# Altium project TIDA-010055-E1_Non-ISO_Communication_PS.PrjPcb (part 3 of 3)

## Sheet TIDA-010055-E1_Non-ISO_Communication_PS_Pg6.SchDoc
size 431 x 279 mm; Date: Not shown in title block; ApprovedBy: Not shown in title block; CheckedBy: Not shown in title block; Author: Not shown in title block; CompanyName: Not shown in title block; Engineer: Not shown in title block; Organization: Not shown in title block; Address1: Not shown in title block; Address2: Not shown in title block; Address3: Not shown in title block; Address4: Not shown in title block; DocumentNumber: 1; Revision: Use project parameter SCH_Rev; SheetNumber: 6; SheetTotal: 7; PageSetup: Record=PageOptions¦CenterHorizontal=True¦CenterVertical=True¦PrintScale=1.00¦XCorrection=1.00¦YCorrection=1.00¦PrintKind=0¦BorderSize=5000000¦LeftOffset=0¦BottomOffset=0¦Orientation=2¦PaperLength=1000¦PaperWidth=1000¦Scale=100¦PaperSource=15¦PrintQuality=600¦MediaType=1¦DitherType=10¦PaperKind=Letter¦PrintScaleMode=1
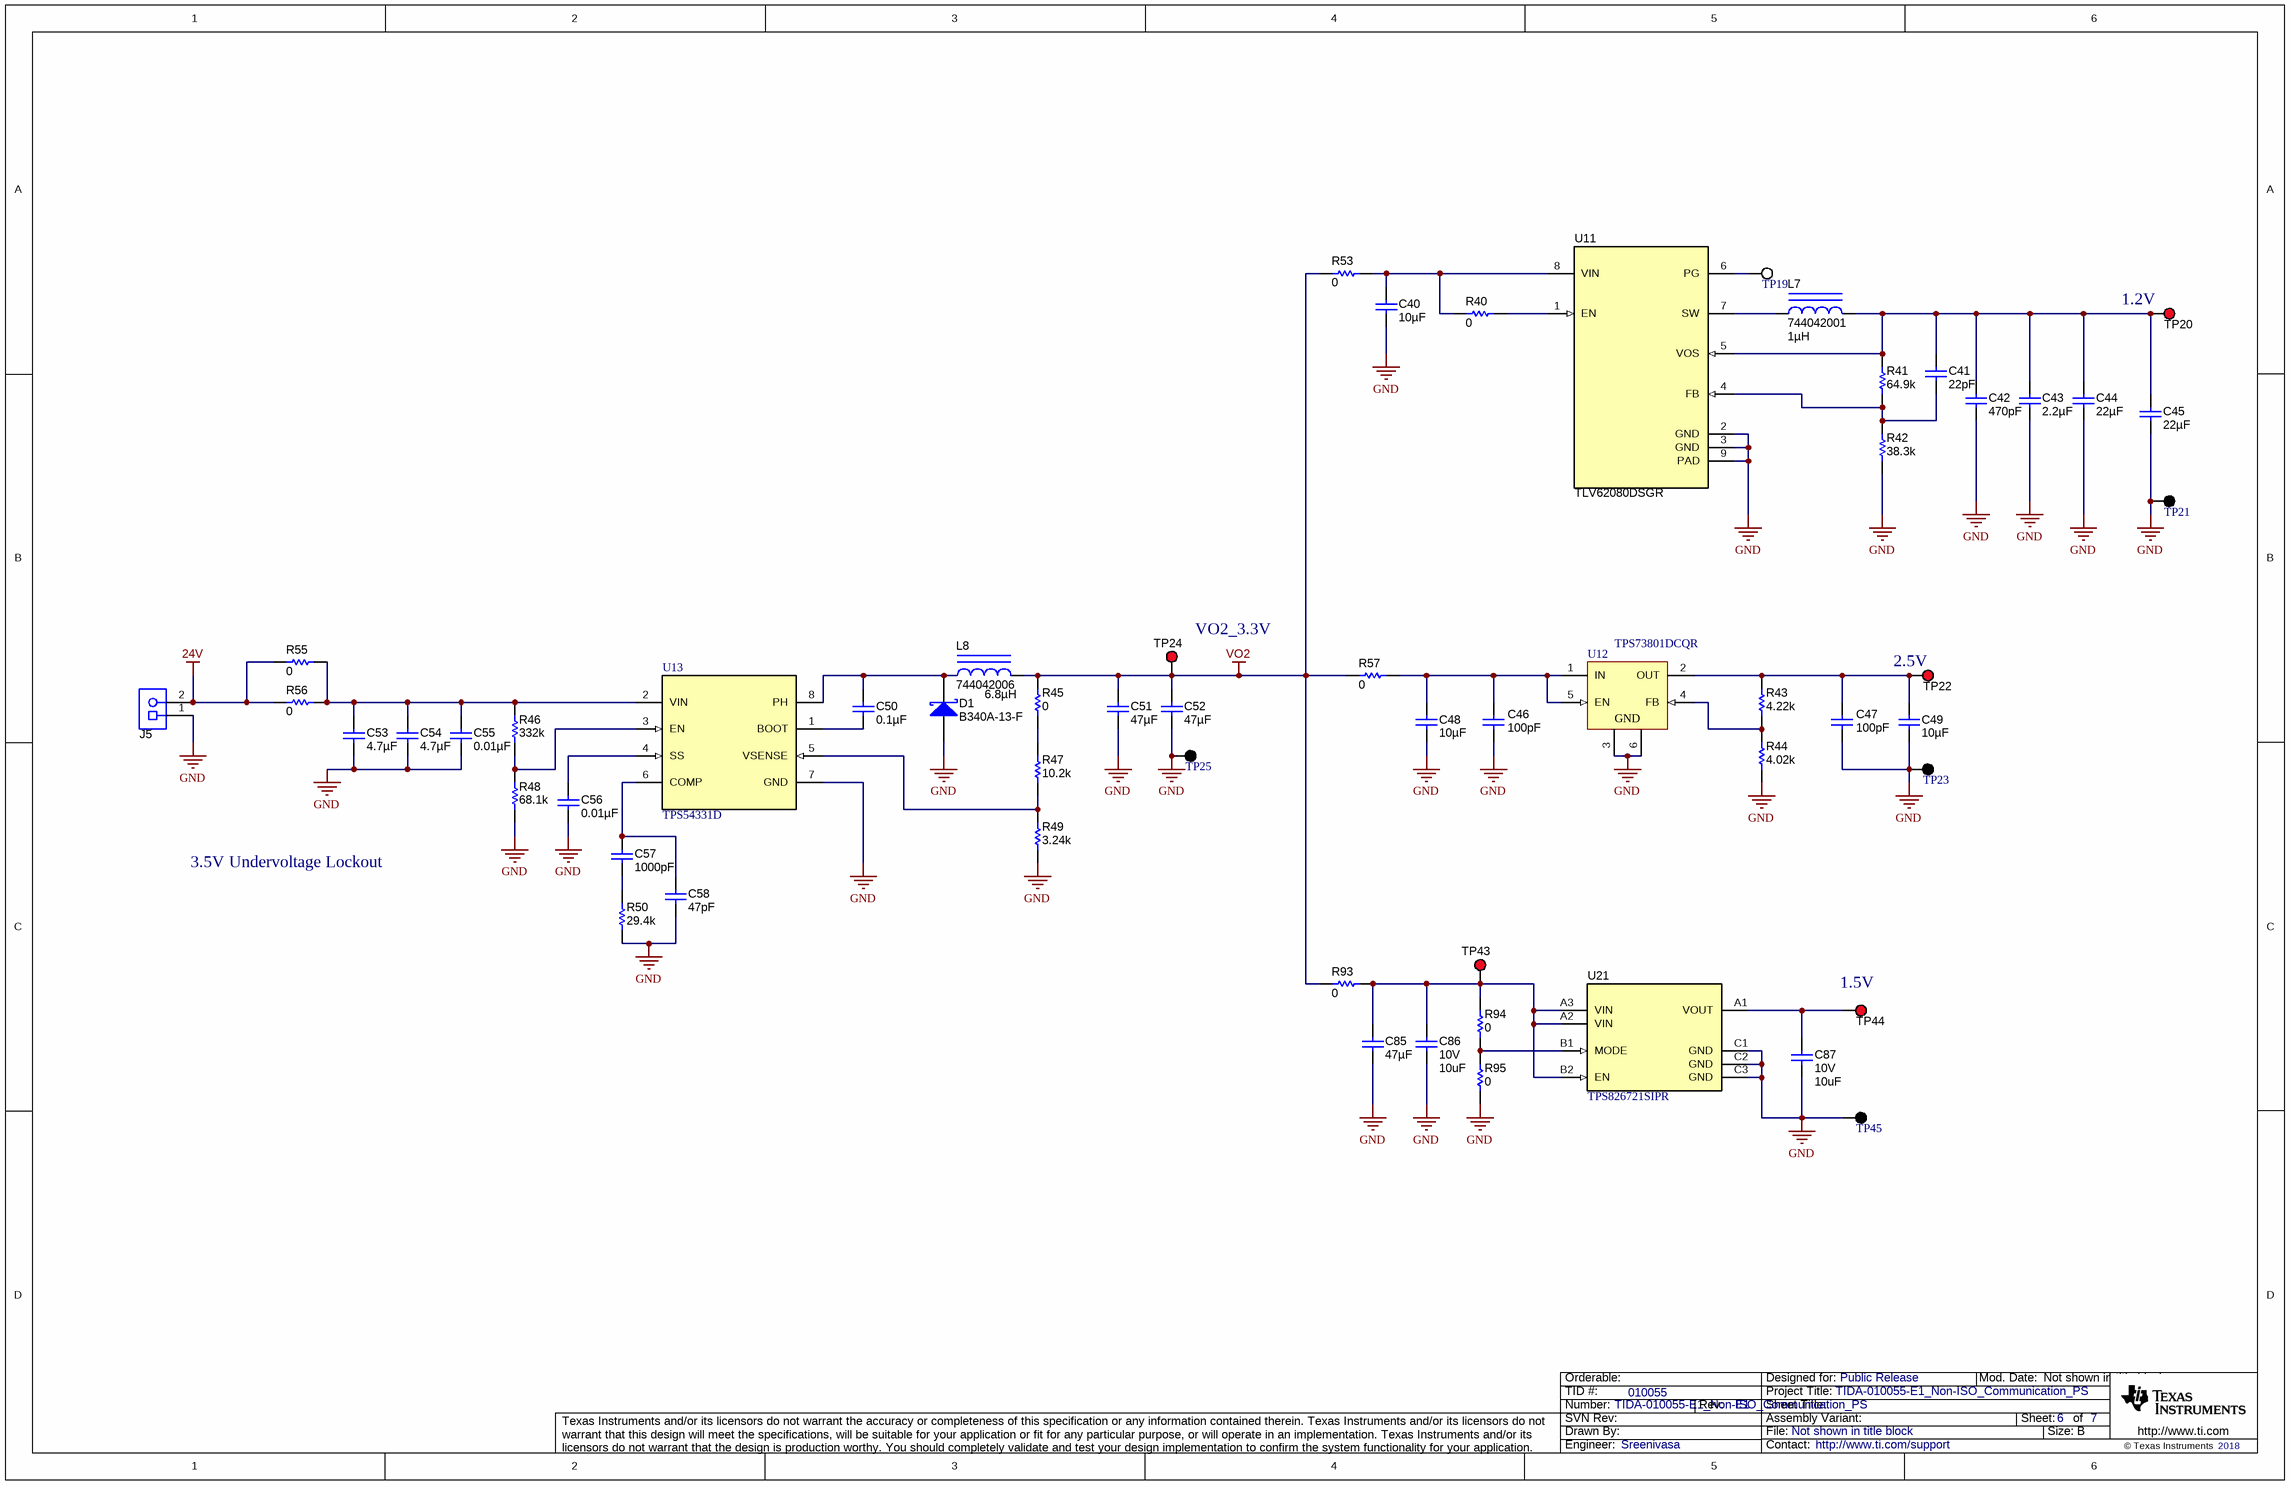
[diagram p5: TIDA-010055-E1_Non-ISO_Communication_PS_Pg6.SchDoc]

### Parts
C40  ValueDisplayed: 10µF  [0603]  (hidden comment: CL10A106MQ8NNNC)
C41  ValueDisplayed: 22pF  [0402]  (hidden comment: CL05C220JB51PNC)
C42  ValueDisplayed: 470pF  [0402]  (hidden comment: GCM155R71H471KA37D)
C43  ValueDisplayed: 2.2µF  [0603]  (hidden comment: 885012106018)
C44  ValueDisplayed: 22µF  [0805_HV1]  (hidden comment: CL21A226KQCLRNC)
C45  ValueDisplayed: 22µF  [0805_HV1]  (hidden comment: CL21A226KQCLRNC)
C46  ValueDisplayed: 100pF  [0603]  (hidden comment: 06031A101GAT2A)
C47  ValueDisplayed: 100pF  [0603]  (hidden comment: 06031A101GAT2A)
C48  ValueDisplayed: 10µF  [0805_HV]  (hidden comment: C2012X5R1E106K085AC)
C49  ValueDisplayed: 10µF  [0805_HV]  (hidden comment: C2012X5R1E106K085AC)
C50  ValueDisplayed: 0.1µF  [0805_HV]  (hidden comment: C0805C104K3RACTU)
C51  ValueDisplayed: 47µF  [0603]  (hidden comment: GRM188R60J476ME15D)
C52  ValueDisplayed: 47µF  [0603]  (hidden comment: GRM188R60J476ME15D)
C53  ValueDisplayed: 4.7µF  [0805_HV]  (hidden comment: C2012X7R1E475K125AB)
C54  ValueDisplayed: 4.7µF  [0805_HV]  (hidden comment: C2012X7R1E475K125AB)
C55  ValueDisplayed: 0.01µF  [0805_HV]  (hidden comment: 08055C103JAT2A)
C56  ValueDisplayed: 0.01µF  [0402]  (hidden comment: C0402C103K4PAC7867)
C57  ValueDisplayed: 1000pF  [0603]  (hidden comment: 06035A102KAT2A)
C58  ValueDisplayed: 47pF  [0603]  (hidden comment: 06035A470KAT2A)
C85  ValueDisplayed: 47µF  [1206_190L]  (hidden comment: CL31A476MPHNNNE)
C86  VDC_V: 10V  ValueDisplayed: 10uF  [0805L]  (hidden comment: GRM21BR71A106ME51L)
C87  VDC_V: 10V  ValueDisplayed: 10uF  [0805L]  (hidden comment: GRM21BR71A106ME51L)
D1  B340A-13-F  [SMA]
J5  1751248  [CONN_1751248]  (value not drawn)
L7  744042001  ValueDisplayed: 1µH  [WE-TPC-M1]
L8  744042006  ValueDisplayed: 6.8µH  [WE-TPC-M1]
R40  ValueDisplayed: 0  [0603]  (hidden comment: CRCW06030000Z0EA)
R41  ValueDisplayed: 64.9k  [0603]  (hidden comment: RC0603FR-0764K9L)
R42  ValueDisplayed: 38.3k  [0603]  (hidden comment: RC0603FR-0738K3L)
R43  ValueDisplayed: 4.22k  [0603]  (hidden comment: CRCW06034K22FKEA)
R44  ValueDisplayed: 4.02k  [0603]  (hidden comment: CRCW06034K02FKEA)
R45  ValueDisplayed: 0  [0603]  (hidden comment: CRCW06030000Z0EA)
R46  ValueDisplayed: 332k  [0603]  (hidden comment: CRCW0603332KFKEA)
R47  ValueDisplayed: 10.2k  [0603]  (hidden comment: CRCW060310K2FKEA)
R48  ValueDisplayed: 68.1k  [0603]  (hidden comment: RC0603FR-0768K1L)
R49  ValueDisplayed: 3.24k  [0603]  (hidden comment: CRCW06033K24FKEA)
R50  ValueDisplayed: 29.4k  [0603]  (hidden comment: RC0603FR-0729K4L)
R53  ValueDisplayed: 0  [5108]  (hidden comment: 5108)
R55  ValueDisplayed: 0  [5108]  (hidden comment: 5108)
R56  ValueDisplayed: 0  [5108]  (hidden comment: 5108)
R57  ValueDisplayed: 0  [5108]  (hidden comment: 5108)
R93  ValueDisplayed: 0  [5108]  (hidden comment: 5108)
R94  ValueDisplayed: 0  [0603]  (hidden comment: CRCW06030000Z0EA)
R95  ValueDisplayed: 0  [0603]  (hidden comment: CRCW06030000Z0EA)
TP19  5002  [Keystone5002]  (value not drawn)
TP20  5000  [Keystone5000]  (value not drawn)
TP21  5001  [Keystone5001]  (value not drawn)
TP22  5000  [Keystone5000]  (value not drawn)
TP23  5001  [Keystone5001]  (value not drawn)
TP24  5000  [Keystone5000]  (value not drawn)
TP25  5001  [Keystone5001]  (value not drawn)
TP43  5000  [Keystone5000]  (value not drawn)
TP44  5000  [Keystone5000]  (value not drawn)
TP45  5001  [Keystone5001]  (value not drawn)
U11  TLV62080DSGR  [DSG0008A]
U12  TPS73801DCQR  [DCQ0006A_N]
U13  TPS54331D  [D0008A_N]
U21  TPS826721SIPR  [SIP0008A]

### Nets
24V: J5.2 R55.2 R56.2
GND: C40.2 C42.2 C43.2 C44.2 C45.2 C46.1 C47.1 C48.1 C49.1 C51.2 C52.2 C53.2 C54.2 C55.2 C56.2 C58.2 C85.2 C86.2 C87.2 D1.2(A) J5.1 R42.1 R44.1 R48.1 R49.1 R50.1 R95.1 TP21.1 TP23.1 TP25.1 TP45.1 U11.2(GND) U11.3(GND) U11.9(PAD) U12.3(GND) U12.6(GND) U13.7(GND) U21.C1(GND) U21.C2(GND) U21.C3(GND)
VO2: C51.1 C52.1 L8.2 R45.2 R53.2 R57.2 R93.2 TP24.1
NetC40_1: C40.1 R40.1 R53.1 U11.8(VIN)
NetC41_1: C41.1 C42.1 C43.1 C44.1 C45.1 L7.2 R41.2 TP20.1 U11.5(VOS)
NetC41_2: C41.2 R41.1 R42.2 U11.4(FB)
NetC46_2: C46.2 C48.2 R57.1 U12.1(IN) U12.5(EN)
NetC47_2: C47.2 C49.2 R43.2 TP22.1 U12.2(OUT)
NetC50_1: C50.1 D1.1(K) L8.1 U13.8(PH)
NetC50_2: C50.2 U13.1(BOOT)
NetC53_1: C53.1 C54.1 C55.1 R46.2 R55.1 R56.1 U13.2(VIN)
NetC56_1: C56.1 U13.4(SS)
NetC57_1: C57.1 C58.1 U13.6(COMP)
NetC57_2: C57.2 R50.2
NetC85_1: C85.1 C86.1 R93.1 R94.2 TP43.1 U21.A2(VIN) U21.A3(VIN) U21.B2(EN)
NetC87_1: C87.1 TP44.1 U21.A1(VOUT)
NetL7_1: L7.1 U11.7(SW)
NetR40_2: R40.2 U11.1(EN)
NetR43_1: R43.1 R44.2 U12.4(FB)
NetR45_1: R45.1 R47.2
NetR46_1: R46.1 R48.2 U13.3(EN)
NetR47_1: R47.1 R49.2 U13.5(VSENSE)
NetR94_1: R94.1 R95.2 U21.B1(MODE)
NetTP19_1: TP19.1 U11.6(PG)

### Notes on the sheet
- (near TP20) 1.2V
- (near TP24) VO2_3.3V
- (near TP22) 2.5V
- 3.5V Undervoltage Lockout
- (near TP44) 1.5V

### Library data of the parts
C40 = GRM188R60J106ME84: CAP, CERM, 10 µF, 6.3 V, +/- 20%, X5R, 0603; Manufacturer: Samsung Electro-Mechanics; Polarized: N; CompType: Capacitor; Value: 10uF; U/M: EA; Cap_F: 0.00001; Tolerance_%: 20; Value1: Unknown; VDC_V: 6.3; Value2: 6.3V; TaMin_C: -55; TaMax_C: 85; AEC Category: Q200
C41 = GRM1555C1H220FA01D: CAP, CERM, 22 pF, 50 V, +/- 1%, C0G/NP0, 0402; Manufacturer: Samsung Electro-Mechanics; Polarized: N; CompType: Capacitor; Value: 22pF; U/M: EA; Cap_F: 0.000000000022; Tolerance_%: 1; Value1: Unknown; VDC_V: 50; Value2: 50V; TaMin_C: -55; TaMax_C: 125; AEC Category: Q200
C42 = GCM155R71H471KA37D: CAP, CERM, 470 pF, 50 V, +/- 10%, X7R, AEC-Q200 Grade 1, 0402; Manufacturer: MuRata; Polarized: N; CompType: Capacitor; Value: 470pF; U/M: EA; Cap_F: 0.00000000047; Tolerance_%: 10; Value1: Unknown; VDC_V: 50; Value2: 50V; TaMin_C: -55; TaMax_C: 125; AEC Category: Q200; AEC Qualified: Y; AEC Grade: 1
C43 = 885012106018: CAP, CERM, 2.2 µF, 16 V,+/- 20%, X5R, 0603; Manufacturer: Wurth Elektronik; Polarized: N; CompType: Capacitor; Value: 2.2uF; U/M: EA; Cap_F: 0.0000022; Tolerance_%: 20; VDC_V: 16; Value2: 16V; TaMin_C: -55; TaMax_C: 85; SizeArea_mm2: 1.28; SizeAreaWB_mm2: 4.68; SizeX_mm: 1.6; SizeY_mm: 0.8; SizeZ_mm: 1; AEC Category: Q200; Green_Lifecycle: Not Set; Green_REACh: Incomplete
C44 C45 = GRM21BR60J226ME39L: CAP, CERM, 22 µF, 6.3 V, +/- 20%, X5R, 0805; Manufacturer: Samsung Electro-Mechanics; Polarized: N; CompType: Capacitor; Value: 22uF; U/M: EA; Cap_F: 0.000022; Tolerance_%: 20; ESR_ohm: 0.009; Value1: 0.009 ohm; VDC_V: 6.3; Value2: 6.3V; IRMS_A: 3.5; TaMin_C: -55; TaMax_C: 85; Cap_Case: 0805; AEC Category: Q200
C46 C47 = 06035A101JAT2A: CAP, CERM, 100 pF, 50 V, +/- 5%, C0G/NP0, 0603; Manufacturer: AVX; Polarized: N; CompType: Capacitor; Value: 100pF; U/M: EA; Cap_F: 0.0000000001; Tolerance_%: 5; ESR_ohm: 0.119; Value1: 0.119 ohm; VDC_V: 50; Value2: 50V; TaMin_C: -55; TaMax_C: 125; SizeArea_mm2: 1.28; SizeAreaWB_mm2: 4.68; SizeX_mm: 1.6; SizeY_mm: 0.8; SizeZ_mm: 1; AEC Category: Q200
C48 C49 = GRM21BR61E106KA73L: CAP, CERM, 10 µF, 25 V, +/- 10%, X5R, 0805; Manufacturer: TDK Corporation; Polarized: N; CompType: Capacitor; Value: 10uF; U/M: EA; Cap_F: 0.00001; Tolerance_%: 10; Value1: Unknown; VDC_V: 25; Value2: 25V; TaMin_C: -55; TaMax_C: 85; Cap_Case: 0805; AEC Category: Q200
C50 = GRM21BR71E104KA01L: CAP, CERM, 0.1 µF, 25 V, +/- 10%, X7R, 0805; Manufacturer: KEMET; Polarized: N; CompType: Capacitor; Value: 0.1uF; U/M: EA; Cap_F: 0.0000001; Tolerance_%: 10; Value1: Unknown; VDC_V: 25; Value2: 25V; TaMin_C: -55; TaMax_C: 125; Cap_Case: 0805; AEC Category: Q200
C51 C52 = GRM188R60J476ME15D: CAP, CERM, 47 µF, 6.3 V,+/- 20%, X5R, 0603; Manufacturer: MuRata; Polarized: N; CompType: Capacitor; Value: 47uF; U/M: EA; Cap_F: 0.000047; Tolerance_%: 20; VDC_V: 6.3; Value2: 6.3V; TaMin_C: -55; TaMax_C: 85; SizeArea_mm2: 1.28; SizeAreaWB_mm2: 4.68; SizeX_mm: 1.6; SizeY_mm: 0.8; SizeZ_mm: 1; AEC Category: Q200; Green_Lifecycle: Active; Green_REACh: Passed
C53 C54 = GRM21BR71E475KA73L: CAP, CERM, 4.7 µF, 25 V,+/- 10%, X7R, 0805; Manufacturer: TDK Corporation; Polarized: N; CompType: Capacitor; Value: 4.7uF; U/M: EA; Cap_F: 0.0000047; Tolerance_%: 10; VDC_V: 25; Value2: 25V; TaMin_C: -55; TaMax_C: 125; Cap_Case: 0805; SizeArea_mm2: 2.5; SizeAreaWB_mm2: 6.75; SizeX_mm: 2; SizeY_mm: 1.25; SizeZ_mm: 1.45; AEC Category: Q200
C55 = 08055C103JAT2A: CAP, CERM, 0.01 µF, 50 V,+/- 5%, X7R, 0805; Manufacturer: AVX; Polarized: N; CompType: Capacitor; Value: 0.01uF; U/M: EA; Cap_F: 0.00000001; Tolerance_%: 5; ESR_ohm: 0.078; Value1: 0.078 ohm; VDC_V: 50; Value2: 50V; TaMin_C: -55; TaMax_C: 125; Cap_Case: 0805; SizeArea_mm2: 2.5; SizeAreaWB_mm2: 6.75; SizeX_mm: 2; SizeY_mm: 1.25; SizeZ_mm: 1.45; AEC Category: Q200; Green_Lifecycle: Active; Green_REACh: Passed
C56 = GRM155R61C103KA01D: CAP, CERM, 0.01 µF, 16 V, +/- 10%, X5R, 0402; Manufacturer: KEMET; Polarized: N; CompType: Capacitor; Value: 0.01uF; U/M: EA; Cap_F: 0.00000001; Tolerance_%: 10; Value1: Unknown; VDC_V: 16; Value2: 16V; TaMin_C: -55; TaMax_C: 85; SizeArea_mm2: 0.5; SizeAreaWB_mm2: 3; SizeX_mm: 1; SizeZ_mm: 0.6; AEC Category: Q200
C57 = 06035A102KAT2A: CAP, CERM, 1000 pF, 50 V,+/- 10%, C0G/NP0, 0603; Manufacturer: AVX; Polarized: N; CompType: Capacitor; Value: 1000pF; U/M: EA; Cap_F: 0.000000001; Tolerance_%: 10; ESR_ohm: 0.048; Value1: 0.048 ohm; VDC_V: 50; Value2: 50V; TaMin_C: -55; TaMax_C: 125; SizeArea_mm2: 1.28; SizeAreaWB_mm2: 4.68; SizeX_mm: 1.6; SizeY_mm: 0.8; SizeZ_mm: 1; AEC Category: Q200; Green_Lifecycle: Active; Green_REACh: Passed
C58 = GRM1885C1H470FA01J: CAP, CERM, 47 pF, 50 V,+/- 1%, C0G/NP0, 0603; Manufacturer: AVX Corporation; Polarized: N; CompType: Capacitor; Value: 47pF; U/M: EA; Cap_F: 0.000000000047; Tolerance_%: 1; VDC_V: 50; Value2: 50V; TaMin_C: -55; TaMax_C: 125; SizeArea_mm2: 1.28; SizeAreaWB_mm2: 4.68; SizeX_mm: 1.6; SizeY_mm: 0.8; AEC Category: Q200; Green_Lifecycle: Not Set; Green_REACh: Incomplete
C85 = C3216X5R1E476M160AC: CAP, CERM, 47 µF, 25 V,+/- 20%, X5R, 1206; Manufacturer: Samsung Electro-Mechanics; Polarized: N; CompType: Capacitor; Value: 47uF; U/M: EA; Cap_F: 0.000047; Tolerance_%: 20; VDC_V: 25; Value2: 25V; TaMin_C: -55; TaMax_C: 85; Cap_Case: 1206; SizeArea_mm2: 5.12; SizeAreaWB_mm2: 10.92; SizeX_mm: 3.2; SizeY_mm: 1.6; SizeZ_mm: 1.9; AEC Category: Q200; Green_Lifecycle: Active; Green_REACh: Passed
C86 C87 = CMP-0008316-2: CAP, CERM, 10 uF, 10 V, +/- 20%, X7R, 0805; Manufacturer: TDK Corporation; PartNumber: C2012X7R1A106M125AC; TaMin_C: -55°C; Polarized: N; SizeAreaWB_mm2: 6.75; Value1: Unknown; U/M: EA; Value: 10uF; TaMax_C: 125°C; SizeZ_mm: 1.45; SizeX_mm: 2; SizeY_mm: 1.25; Cap_Case: 0805; SizeArea_mm2: 2.5; CompType: Capacitor; Cap_F: 10µF; AEC Category: Q200
D1 = CMP-0028353-1: Diode, Schottky, 40 V, 3 A, SMA; Manufacturer: Diodes Inc.; Io_A: 3A; Green_Lifecycle: Active; SizeAreaWB_mm2: 37.3428; Vr_V: 40V; Green_REACh: Passed; TJmax_C: 125°C; U/M: EA; Value: 40V; SizeZ_mm: 2.87; SizeX_mm: 5.59; SizeY_mm: 2.92; Vf_V: 5dV; Value2: 0.5V; SizeArea_mm2: 16.3228; AEC Category: Q101; RJC_CperW: 25
J5 = 1751248: Conn Term Block, 2POS, 3.5mm, TH; Manufacturer: Phoenix Contact; CompType: Terminal Block; SymbolCreator: a0412235
L7 = 744042001: Inductor, Shielded Drum Core, Ferrite, 1uH, 2.6A, 0.028 ohm, SMD; Manufacturer: Wurth Elektronik eiSos; Ind_H: 1.0E-6; Imax_A: 2.6; Irms: 2.7A @ 30C rise; Isat: 2.6A @ 35% inductance drop; DCR_ohm: 0.028; U/M: EA
L8 = 744042006: Inductor, Shielded Drum Core, Ferrite, 6.8uH, 1.2A, 0.095 ohm, SMD; Manufacturer: Wurth Elektronik eiSos; Ind_H: 6.8E-6; Imax_A: 1.2; Irms: 1.5A @ 30C rise; Isat: 1.2A @ 35% inductance drop; DCR_ohm: 0.095; U/M: EA
R40 R45 R94 R95 = CRCW06030000Z0EA: RES, 0, 5%, 0.1 W, 0603; Manufacturer: Vishay-Dale; CompType: Resistor; Value: 0; Value_Code: 0000; Tolerance_%: 5; Power_W: 0.1; Value2: 0.1W; VDC_V: 75; TempCo: 200 ppm/C; EIA_Code: E24; U/M: EA; AEC Category: Q200
R41 = RC0603FR-0764K9L: RES, 64.9 k, 1%, 0.1 W, 0603; Manufacturer: Yageo America; CompType: Resistor; Value: 64.9k; Res_ohm: 64900; Value_Code: 64k9; Tolerance_%: 1; Power_W: 0.1; Value2: 0.1W; VDC_V: 150; TempCo: 200 ppm/C; EIA_Code: E96; U/M: EA; AEC Category: Q200; SizeArea_mm2: 1.28; SizeX_mm: 1.6; SizeY_mm: 0.8
R42 = RC0603FR-0738K3L: RES, 38.3 k, 1%, 0.1 W, 0603; Manufacturer: Yageo America; CompType: Resistor; Value: 38.3k; Res_ohm: 38300; Value_Code: 38k3; Tolerance_%: 1; Power_W: 0.1; Value2: 0.1W; VDC_V: 150; TempCo: 200 ppm/C; EIA_Code: E96; U/M: EA; AEC Category: Q200; SizeArea_mm2: 1.28; SizeX_mm: 1.6; SizeY_mm: 0.8; Green_Lifecycle: Active; Green_REACh: Passed
R43 = CRCW06034K22FKEA: RES, 4.22 k, 1%, 0.1 W, 0603; Manufacturer: Vishay-Dale; CompType: Resistor; Value: 4.22k; Res_ohm: 4220; Value_Code: 4k22; Tolerance_%: 1; Power_W: 0.1; Value2: 0.1W; VDC_V: 75; TempCo: 100 ppm/C; SizeArea_mm2: 1.28; SizeX_mm: 1.6; SizeY_mm: 0.8; EIA_Code: E96; U/M: EA; AEC Category: Q200; Green_Lifecycle: Active; Green_REACh: Passed
R44 = CRCW06034K02FKEA: RES, 4.02 k, 1%, 0.1 W, 0603; Manufacturer: Vishay-Dale; CompType: Resistor; Value: 4.02k; Res_ohm: 4020; Value_Code: 4k02; Tolerance_%: 1; Power_W: 0.1; Value2: 0.1W; VDC_V: 75; TempCo: 100 ppm/C; SizeArea_mm2: 1.28; SizeX_mm: 1.6; SizeY_mm: 0.8; EIA_Code: E96; U/M: EA; AEC Category: Q200; Green_Lifecycle: Active; Green_REACh: Passed
R46 = CRCW0603332KFKEA: RES, 332 k, 1%, 0.1 W, 0603; Manufacturer: Vishay-Dale; CompType: Resistor; Value: 332k; Res_ohm: 332000; Tolerance_%: 1; Power_W: 0.1; Value2: 0.1W; VDC_V: 75; TempCo: 100 ppm/C; SizeArea_mm2: 1.28; SizeX_mm: 1.6; SizeY_mm: 0.8; EIA_Code: E96; U/M: EA; AEC Category: Q200; Green_Lifecycle: Active; Green_REACh: Passed
R47 = CRCW060310K2FKEA: RES, 10.2 k, 1%, 0.1 W, 0603; Manufacturer: Vishay-Dale; CompType: Resistor; Value: 10.2k; Res_ohm: 10200; Value_Code: 10k2; Tolerance_%: 1; Power_W: 0.1; Value2: 0.1W; VDC_V: 75; TempCo: 100 ppm/C; SizeArea_mm2: 1.28; SizeX_mm: 1.6; SizeY_mm: 0.8; EIA_Code: E96; U/M: EA; AEC Category: Q200; Green_Lifecycle: Active; Green_REACh: Passed
R48 = RC0603FR-0768K1L: RES, 68.1 k, 1%, 0.1 W, 0603; Manufacturer: Yageo America; CompType: Resistor; Value: 68.1k; Res_ohm: 68100; Value_Code: 68k1; Tolerance_%: 1; Power_W: 0.1; Value2: 0.1W; VDC_V: 150; TempCo: 200 ppm/C; SizeArea_mm2: 1.28; SizeX_mm: 1.6; SizeY_mm: 0.8; EIA_Code: E96; U/M: EA; AEC Category: Q200
R49 = CRCW06033K24FKEA: RES, 3.24 k, 1%, 0.1 W, 0603; Manufacturer: Vishay-Dale; CompType: Resistor; Value: 3.24k; Res_ohm: 3240; Value_Code: 3k24; Tolerance_%: 1; Power_W: 0.1; Value2: 0.1W; VDC_V: 75; TempCo: 100 ppm/C; SizeArea_mm2: 1.28; SizeX_mm: 1.6; SizeY_mm: 0.8; EIA_Code: E96; U/M: EA; AEC Category: Q200; Green_Lifecycle: Active; Green_REACh: Passed
R50 = RC0603FR-0729K4L: RES, 29.4 k, 1%, 0.1 W, 0603; Manufacturer: Yageo America; CompType: Resistor; Value: 29.4k; Res_ohm: 29400; Value_Code: 29k4; Tolerance_%: 1; Power_W: 0.1; Value2: 0.1W; VDC_V: 150; TempCo: 200 ppm/C; SizeArea_mm2: 1.28; SizeX_mm: 1.6; SizeY_mm: 0.8; EIA_Code: E96; U/M: EA; AEC Category: Q200; Green_Lifecycle: Active; Green_REACh: Passed
R53 R55-R57 R93 = 5108: RES, 0, 1%, 0.5 W, 1206; Manufacturer: Keystone; CompType: Resistor; Value: 0; Tolerance_%: 1; Power_W: 0.5; Value2: 0.5W; TempCo: ppm/C; SizeArea_mm2: 5.185; SizeX_mm: 3.05; SizeY_mm: 1.7; SizeZ_mm: 0.84; U/M: EA; AEC Category: Q200; AEC Qualified: N
TP19 = 5002: Test Point, Miniature, White, TH; Manufacturer: Keystone; CompType: Test Point Loop; ContactFinish: Silver; Green_Lifecycle: Active; Green_REACh: Passed
TP20 TP22 TP24 TP43 TP44 = 5000: Test Point, Miniature, Red, TH; Manufacturer: Keystone; CompType: Test Point Loop; ContactFinish: Silver
TP21 TP23 TP25 TP45 = 5001: Test Point, Miniature, Black, TH; Manufacturer: Keystone; CompType: Test Point Loop; ContactFinish: Silver; Green_Lifecycle: Active; Green_REACh: Passed
U11 = TLV62080DSGR: 1.2A High Efficient Step Down Converter in 2x2mm SON Package, DSG0008A (WSON-8); Alternate PartNumber: TLV62080DSGT; Manufacturer: Texas Instruments; SymbolCreator: a0411947; SizeArea_mm2: 4; SizeAreaWB_mm2: 9; SizeX_mm: 2; SizeZ_mm: 0.8; CompType: IC; U/M: EA
U12 = CMP-0036669-1: Single Output Fast Transient Response LDO, 1 A, Adjustable 1.2 to 20 V Output, 2.2 to 20 V Input, 6-pin SOT-223 (DCQ), -40 to 125 degC, Green (RoHS & no Sb/Br); Manufacturer: Texas Instruments; Vout Adj(Max)(V): 20; Iout(Max)(A): 1; Vdo(Typ)(mV): 300; SubFamily: Single Channel LDO; Vin(Min)(V): 2.2; Vout Adj(Min)(V): 1.2
U13 = CMP-0037667-1: Buck Step Down Regulator with 3.5 to 28 V Input and 0.8 to 25 V Output, -40 to 150 degC, 8-Pin SOIC (D), Green (RoHS & no Sb/Br); Manufacturer: Texas Instruments; Iq(Typ)(mA): 0.11; Duty Cycle(Max)(%): 90; Vout(Max)(V): 25; Rating: Catalog; Vin(Min)(V): 3.5; Iout(Max)(A): 3; Regulated Outputs(#): 1; Vin(Max)(V): 28; Vout(Min)(V): 0.8; SubFamily: Step-Down Regulator
U21 = CMP-0081865-1: 600mA Fully Integrated, Low Noise Step-Down Converter Module in MicroSiP(TM) Package, SIP0008A (uSIP-8); Alternate PartNumber: TPS826721SIPT; Alternate Manufacturer: Texas Instruments; SizeAreaWB_mm2: 12.87; Rating: Catalog; SizeZ_mm: 1; SizeX_mm: 2.9; SizeY_mm: 2.3; SizeArea_mm2: 6.67; CompType: IC; AEC Qualified: N; AEC Category: Q200

## Sheet TIDA-010055-E1_Non-ISO_Communication_PS_EVM_Hardware_Pg6.SchDoc: Hardware
size 431 x 279 mm; Date: Not shown in title block; ApprovedBy: Not shown in title block; CheckedBy: Not shown in title block; Author: Not shown in title block; CompanyName: Not shown in title block; DrawnBy: Sreenivasa; Engineer: Not shown in title block; Organization: Not shown in title block; Address1: Not shown in title block; Address2: Not shown in title block; Address3: Not shown in title block; Address4: Not shown in title block; DocumentNumber: 1; Revision: Use project parameter SCH_Rev; SheetNumber: 7; SheetTotal: 7; PageSetup: Record=PageOptions¦CenterHorizontal=True¦CenterVertical=True¦PrintScale=1.00¦XCorrection=1.00¦YCorrection=1.00¦PrintKind=0¦BorderSize=5000000¦LeftOffset=0¦BottomOffset=0¦Orientation=2¦PaperLength=1000¦PaperWidth=1000¦Scale=100¦PaperSource=15¦PrintQuality=600¦MediaType=1¦DitherType=10¦PaperKind=Letter¦PrintScaleMode=1
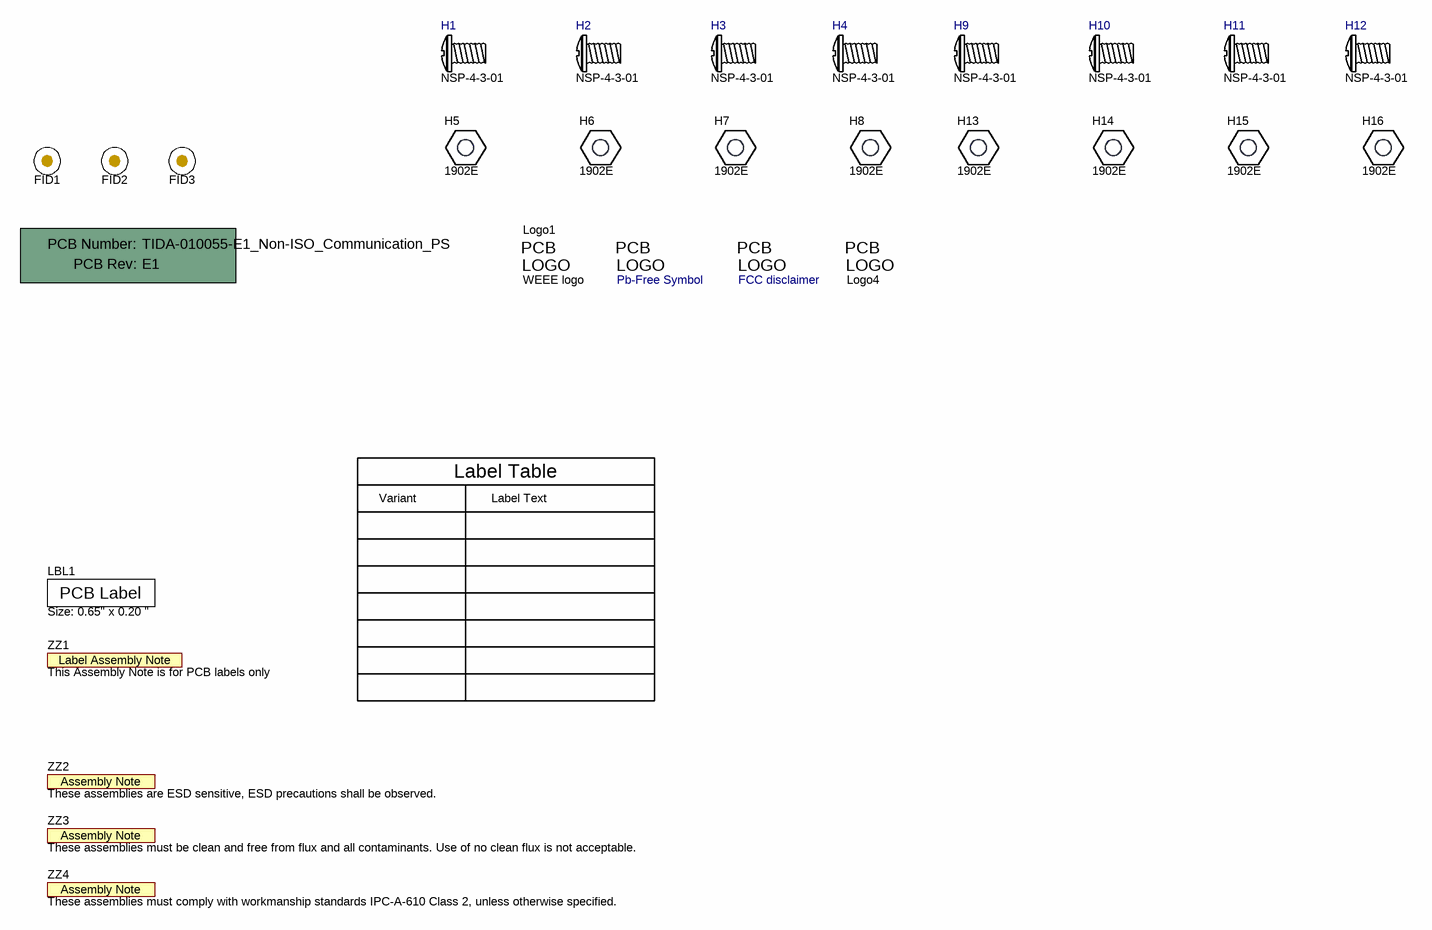
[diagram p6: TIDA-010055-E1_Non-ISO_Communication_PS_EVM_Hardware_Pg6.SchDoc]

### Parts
!PCB1  Printed Circuit Board  (value not drawn)  (mechanical)
FID1  Fiducial  [Fiducial10-30]  (value not drawn)
FID2  Fiducial  [Fiducial10-30]  (value not drawn)
FID3  Fiducial  [Fiducial10-30]  (value not drawn)
H1  NSP-4-3-01  [B_F_PMSSS4400025PH]
H2  NSP-4-3-01  [B_F_PMSSS4400025PH]
H3  NSP-4-3-01  [B_F_PMSSS4400025PH]
H4  NSP-4-3-01  [B_F_PMSSS4400025PH]
H5  1902E  [Keystone_1902E]
H6  1902E  [Keystone_1902E]
H7  1902E  [Keystone_1902E]
H8  1902E  [Keystone_1902E]
H9  NSP-4-3-01  [B_F_PMSSS4400025PH]
H10  NSP-4-3-01  [B_F_PMSSS4400025PH]
H11  NSP-4-3-01  [B_F_PMSSS4400025PH]
H12  NSP-4-3-01  [B_F_PMSSS4400025PH]
H13  1902E  [Keystone_1902E]
H14  1902E  [Keystone_1902E]
H15  1902E  [Keystone_1902E]
H16  1902E  [Keystone_1902E]
LBL1  Size: 0.65" x 0.20 "  [Label_650x200]
Logo1  WEEE logo  [WEEE_Minimum]  (no BOM)
Logo2  Pb-Free Symbol  [Pb-Free_Overlay_Small]  (no BOM)
Logo3  FCC disclaimer  [FCC_disclaimer_stacked]  (no BOM)
Logo4  ESD Susceptible  [ESD_Overlay_Medium]  (value not drawn)  (no BOM)
ZZ1  This Assembly Note is for PCB labels only  [AssemblyNoteLabel]  (no BOM)
ZZ2  These assemblies are ESD sensitive, ESD precautions shall be observed.  [AssemblyNote]  (no BOM)
ZZ3  These assemblies must be clean and free from flux and all contaminants. Use of no clean flux is not acceptable.  [AssemblyNote]  (no BOM)
ZZ4  These assemblies must comply with workmanship standards IPC-A-610 Class 2, unless otherwise specified.  [AssemblyNote]  (no BOM)

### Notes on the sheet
- Variant
- Label Table
- Label Text

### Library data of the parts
!PCB1 = PCB: Manufacturer: Any; PartNumber: TIDA-010055-E1_Non-ISO_Communication_PS; SymbolCreator: a0412235
FID1-FID3 = Fiducial: Fiducial mark.  There is nothing to buy or mount.; SymbolCreator: codlsc
H1-H4 H9-H12 = PMSSS 440 0025 PH: MACHINE SCREW PAN PHILLIPS 4-40; Manufacturer: Essentra Components; CompType: Standoff; SymbolCreator: a0412235
H5-H8 H13-H16 = 1902E: Standoff, Hex, 1"L #4-40 Nylon; Manufacturer: Keystone; CompType: Hardware; SymbolCreator: a0412235
LBL1 = THT-14-423-10: Thermal Transfer Printable Labels, 0.650" W x 0.200" H - 10,000 per roll; Manufacturer: Brady; SymbolCreator: a0412235; CompType: Label
Logo1 = CMP-0074769-1
Logo2 = Pb-Free: SymbolCreator: a0412235
Logo3 = FCC_disclaimer: SymbolCreator: codlsc
Logo4 = ESD_Susceptible: ESD Susceptible Symbol; SymbolCreator: a0412235
ZZ1 = AssemblyNoteLabel: SymbolCreator: a0412235
ZZ2-ZZ4 = AssemblyNote: SymbolCreator: codlsc

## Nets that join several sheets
24V: TIDA-010055-E1_Non-ISO_Communication_PS_Pg5 (R54.2 R82.2), TIDA-010055-E1_Non-ISO_Communication_PS_Pg6 (J5.2 R55.2 R56.2)
DC_I: TIDA-010055-E1_Non-ISO_Communication_PS_Pg3 (10 pins), TIDA-010055-E1_Non-ISO_Communication_PS_Pg4 (R51.2)
GND: TIDA-010055-E1_Non-ISO_Communication_PS_Pg5 (42 pins), TIDA-010055-E1_Non-ISO_Communication_PS_Pg6 (40 pins)
GND_P: TIDA-010055-E1_Non-ISO_Communication_PS_Pg3 (54 pins), TIDA-010055-E1_Non-ISO_Communication_PS_Pg4 (33 pins)

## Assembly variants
001: not fitted FID1 FID2 FID3 R95 R99 R102 R103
